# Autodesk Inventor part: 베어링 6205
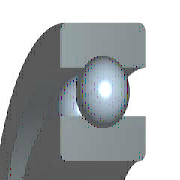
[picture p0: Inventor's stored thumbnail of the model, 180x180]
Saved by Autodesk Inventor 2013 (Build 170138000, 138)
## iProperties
Created: 2009-02
Part Number: 베어링 6205
Material: 강, 연강
Description: 깊은 그루브 볼 베어링
Document SubType Name: Modeling
Standard: KS B 2023
Designer: SeoGD™[esajin.kr]
Standards Organization: KS
Language: ko-KR
Size Designation: 6205 - 25 x 52 x 15
Categories: <MemberInstance><Categories><Category DisplayName="샤프트 부품" InternalName="7f7aeb1f-a693-4053-b835-cee3144e0d98" Mnemonic="SHFT"><Category DisplayName="베어링" Inter
Density: 7.86 g/cm^3
Mass: 129.543 g
Surface Area: 107.326 cm^2
Volume: 16.4813 cm^3
IsCustomPart: 1
Author: SeoGD™[esajin.kr]
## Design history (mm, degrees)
sketch "스케치" dims "d0" = 7.02 (= -0.26 x WD + 0.26 x BD)
  geometry: L1 (3.99, 19.25)-(11.01, 19.25); L2 (7.5, 19.25)-(7.5, 15.74); L3 (7.5, 19.25)-(7.5, 22.76); L4 (4.892, 16.901)-(0, 16.901); L5 (0, 12.5)-(15, 12.5); L6 (4.892, 21.599)-(0, 21.599); L7 (0, 26)-(15, 26); L8 (15, 12.5)-(15, 16.901); L9 (10.108, 16.901)-(15, 16.901); L10 (10.108, 21.599)-(15, 21.599); L11 (15, 26)-(15, 21.599); L12 (-1.4, 0)-(8.4, 0) reference; L13 (0, -0.3)-(0, 5.3) reference
  constraints: 22 end point, 4 point on line, 2 collinear, 2 perpendicular, 2 symmetric about line, 1 midpoint, 1 parallel, 14 other
  dimensions: "d9" = 25 diameter of L5 L12 (= WD); "d11" = 52 diameter of L7 L12 (= BD); "d12" = 15 distance between parallel lines of L8 L13 (= KB); "d13" = 33.802 diameter of L9 L12 (= 0.326 x BD + 0.674 x WD)
revolve "본체" stored, may be unused: angle "d6" = 90 deg
revolve "볼" stored, may be unused: angle "d7" = 90 deg
pattern_circular "IDS_ARRAYBALL[SIMPL:T]" dims angle "d3" = 360 deg
body "Solid1"
fillet "모깎기1" dims "d1" = 1 (= KRS)
other parameters: "WD" = 25 [user parameter; used in 5 equation terms], "BD" = 52 [user parameter; used in 5 equation terms], "KB" = 15 [user parameter; used in 1 equation term], "KRS" = 1 [user parameter; used in 1 equation term], "d4" = 0, "d5" = 0, "d8" = 0, "d14" = 0, "d15" = 0, "BBA" = 0 [user parameter], "BC0" = 7800000 [user parameter], "BC" = 1.4e+07 [user parameter], "BR" = 26 (= 0.5 x BD) [user parameter], "WR" = 12.5 (= 0.5 x WD) [user parameter]
